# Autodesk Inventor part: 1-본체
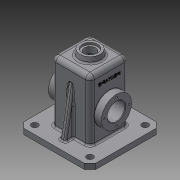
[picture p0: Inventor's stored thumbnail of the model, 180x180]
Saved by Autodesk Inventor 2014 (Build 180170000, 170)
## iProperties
Created: 2016-02
Part Number: 1-본체
Material: 일반
Document SubType Name: Modeling
Designer: G.C.Oh
Density: 1 g/cm^3
Appearance: 기본값
Author: G.C.Oh
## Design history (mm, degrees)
sketch "스케치1"
  geometry: L1 (65, -65)-(-65, -65); L2 (-65, -65)-(-65, 65); L3 (-65, 65)-(65, 65); L4 (65, 65)-(65, -65); L5 (65, -65)-(-65, 65); L6 (-65, -65)-(65, 65); 1 further point
  constraints: 12 end point, 2 midpoint, 2 parallel, 1 horizontal, 1 perpendicular
  dimensions: "d0" = 130 distance of L2.end L3.end; "d1" = 130 distance of L1.end L2.end
extrude "돌출1" new body sketch "스케치1" distance "d2" = 10; taper "d3" = 0 deg
sketch "스케치2"
  geometry: L1 (-35, -35)-(35, -35); L2 (35, -35)-(35, 35); L3 (35, 35)-(-35, 35); L4 (-35, 35)-(-35, -35); L5 (-35, -35)-(35, 35); L6 (35, -35)-(-35, 35); 1 further point
  constraints: 12 end point, 2 midpoint, 2 parallel, 1 horizontal, 1 perpendicular
  dimensions: "d4" = 70 distance of L1.end L2.end; "d5" = 70 distance of L2.end L3.end
extrude "돌출2" join sketch "스케치2" distance "d6" = 110; taper "d7" = 0 deg
sketch "스케치3"
  geometry: L1 (0, 120)-(-20, 120); L2 (-20, 120)-(-18.237, 130); L3 (-18.237, 130)-(0, 130); L4 (0, 130)-(0, 120); L5 (-35, 10)-(-35, 120) reference; L6 (-35, 120)-(35, 120) reference; 1 further point
  constraints: 8 end point, 1 collinear, 1 horizontal, 1 parallel, 1 perpendicular, 1 vertical alignment
  dimensions: "d9" = 40 diameter of L1.end L4; "d10" = 10 deg angle of L5 L2; "d11" = 10 distance between parallel lines of L1 L3
revolve "회전1" sketch "스케치3" stored, may be unused: angle "d12" = 90 deg
fillet "모깎기1" dims "d13" = 8
sketch "스케치4"
  geometry: C1 r 27.5 at (0, 55); 1 further point
  constraints: 1 centre point, 1 vertical alignment
  dimensions: "d14" = 55 distance of point (0, 0) C1.centre; "d15" = 55 diameter of C1
extrude "돌출3" join sketch "스케치4" stored distance "d16" = 96; taper "d17" = 0 deg
sketch "스케치5"
  geometry: L1 (30, 0)-(-30, 0); L2 (-30, 0)-(-30, 115); L3 (-30, 115)-(30, 115); L4 (30, 115)-(30, 0); L5 (35, 10)-(35, 49.78) reference; L6 (-35, 49.78)-(-35, 10) reference; L7 (-27, 120)-(27, 120) reference; 1 further point
  constraints: 8 end point, 2 parallel, 1 horizontal, 1 midpoint, 1 perpendicular
  dimensions: "d18" = 5 distance between parallel lines of L5 L4; "d19" = 5 distance between parallel lines of L6 L2; "d20" = 5 distance between parallel lines of L7 L3
extrude "돌출4" cut sketch "스케치5" stored distance "d21" = 60; taper "d22" = 0 deg
fillet "모깎기2" dims "d23" = 8
hole "구멍1" diameter "d26" = 21; stored, may be unused: countersink angle "d30" = 90 deg, drill point angle "d32" = 118 deg; dims "d24" = 10, "d25" = 10, "d27" = 6, "d28" = 28, "d29" = 4, "d31" = 8
sketch "스케치6"
  geometry: L1 (-30, 82.5)-(-23, 75.5); L2 (-23, 75.5)-(-23, 55); L3 (-23, 55)-(-30, 55); L4 (-30, 55)-(-30, 82.5); L5 (-30, 115)-(-30, 0) reference; L6 (-35, 82.5)-(-48, 82.5) reference; 1 further point
  constraints: 8 end point, 2 perpendicular, 1 collinear, 1 point on line, 1 vertical
  dimensions: "d33" = 55 diameter of L1.start L3; "d34" = 7 distance between parallel lines of L4 L2; "d35" = 135 deg angle of L5 L1
revolve "회전2" sketch "스케치6" stored, may be unused: angle "d36" = 90 deg
sketch "스케치7"
  geometry: L1 (0, 0)-(-22.5, 0); C1 r 27.5 at (0, 0) reference; 1 further point
  constraints: 2 end point, 1 horizontal
  dimensions: "d37" = 22.5 distance of L1.start L1.end
hole "구멍2" sketch "스케치7" at (-22.5, 0) diameter "d38" = 3.242; stored, may be unused: countersink angle "d42" = 90 deg, drill point angle "d44" = 118 deg; dims "d39" = 8, "d40" = 28, "d41" = 4, "d43" = 10
hole "구멍3" diameter "d50" = 32; stored, may be unused: countersink angle "d54" = 90 deg, drill point angle "d56" = 118 deg; dims "d48" = 10, "d49" = 10, "d51" = 8, "d52" = 28, "d53" = 4, "d55" = 10
sketch "스케치8"
  geometry: L1 (50, 10)-(39.934, 67.084); L2 (-65, 10)-(65, 10) reference; L3 (65, 0)-(65, 10) reference; 1 further point
  constraints: 2 end point, 1 point on line
  dimensions: "d57" = 15 distance from line of L3 L1.start; "d58" = 10 deg angle of L3 L1
feature "리브1" sketch "스케치8" dims "d59" = 1, "d60" = 10, "d61" = 0, "d62" = 0, "d63" = 1, "d64" = 1
chamfer "모따기1" distance "d65" = 10; stored, may be unused: second distance "d66" = 2, angle "d67" = 45 deg
sketch "스케치9"
  geometry: L1 (50, -50)-(-50, -50); L2 (-50, -50)-(-50, 50); L3 (-50, 50)-(50, 50); L4 (50, 50)-(50, -50); L5 (50, -50)-(-50, 50); L6 (-50, -50)-(50, 50); 1 further point
  constraints: 12 end point, 2 midpoint, 2 parallel, 1 horizontal, 1 perpendicular
  dimensions: "d68" = 100 distance of L2.end L3.end; "d69" = 100 distance of L1.end L2.end
hole "구멍4" sketch "스케치9" at (-50, 50), (-50, -50), (50, -50), (50, 50) diameter "d70" = 12; stored, may be unused: countersink angle "d74" = 90 deg, drill point angle "d76" = 118 deg; dims "d71" = 8, "d72" = 28, "d73" = 4, "d75" = 10
fillet "모깎기3" dims "d77" = 0.5
sketch "스케치10"
  geometry: L1 (102, 62)-(0, 62) reference; L2 (-18, 45.237)-(-18, 8.763) reference; 2 further points
  constraints: 1 other
  dimensions: "d78" = 35 distance from line of L1 point (12, 27); "d79" = 30 distance from line of L2 point (12, 27)
feature "엠보싱1" sketch "스케치10" dims "d0" = 130, "d1" = 130, "d80" = 0.5, "d81" = 0
fillet "모깎기4" dims "d82" = 3
fillet "모깎기5" dims "d83" = 3
chamfer "모따기2" distance "d84" = 1; stored, may be unused: second distance "d85" = 2, angle "d86" = 45 deg
fillet "모깎기6" dims "d87" = 3
fillet "모깎기7" dims "d88" = 3
fillet "모깎기8" dims "d89" = 3
node "솔리드1"
pattern_circular "원형 패턴1" dims angle "d46" = 360 deg
mirror "대칭1"
mirror "대칭2"
